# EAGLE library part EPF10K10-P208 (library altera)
EPF10K10 FLEX 10K family
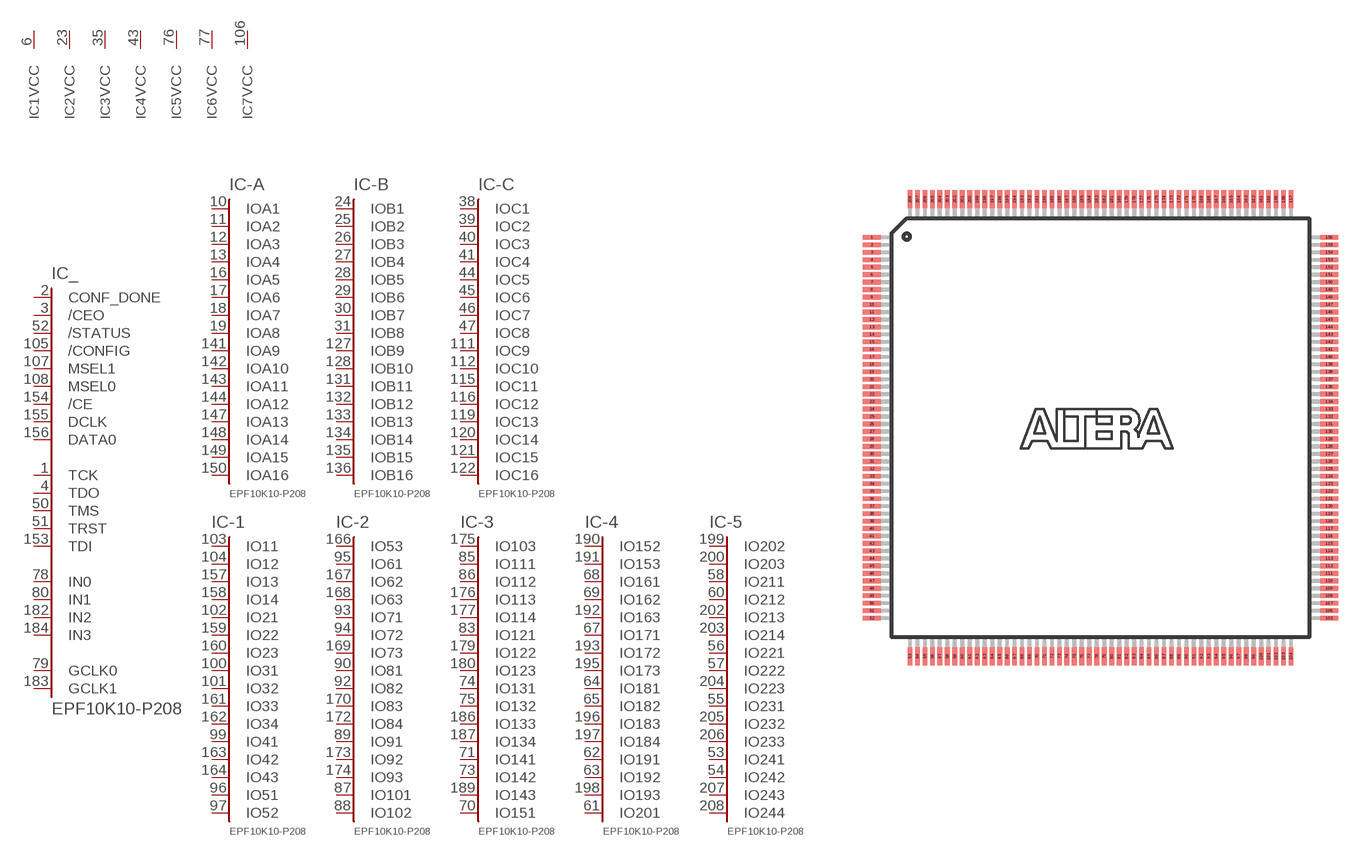
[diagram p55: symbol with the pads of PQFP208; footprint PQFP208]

Designator prefix IC; gates _=K10-CTRL -A=A16 -B=B16 -C=C16 -1=52-K10 -2=102-K10 -3=151-K10 -4=201-K10 -5=244-K10 1=VCCINT 2=VCCINT 3=VCCINT 4=VCCINT 5=VCCINT 6=VCCINT 7=VCCINT 8=VCCINT 9=VCCINT 10=VCCINT 11=VCCINT 12=VCCINT 13=VCCIO 14=VCCIO 15=VCCIO 16=VCCIO 17=VCCIO 18=VCCIO 19=VCCIO 20=VCCIO 21=VCCIO 22=VCCIO 23=VCCIO 24=VCCIO 25=VCCIO 26=VCCIO 27=GNDINT 28=GNDINT 29=GNDINT 30=GNDINT 31=GNDINT 32=GNDINT 33=GNDINT 34=GNDINT 35=GNDINT 36=GNDIO 37=GNDIO 38=GNDIO 39=GNDIO 40=GNDIO 41=GNDIO 42=GNDIO 43=GNDIO 44=GNDIO 45=GNDIO 46=GNDIO 47=GNDIO NC1=NC NC2=NC NC3=NC NC4=NC NC5=NC NC6=NC NC7=NC NC8=NC NC9=NC NC10=NC NC11=NC NC12=NC NC13=NC

## EPF10K10-P208 (MPN: EPF10K10AQC208-3N; OC_FARNELL: 1549381; OC_NEWARK: 51R8749)  [PQFP208]
1  _:TCK
2  _:CONF_DONE  in
3  _:/CEO  in
4  _:TDO
5  13:VCCIO  pwr
6  1:VCC  pwr
7  NC1:NC  nc
8  NC2:NC  nc
9  NC3:NC  nc
10  -A:IOA1
11  -A:IOA2
12  -A:IOA3
13  -A:IOA4
14  NC4:NC  nc
15  NC5:NC  nc
16  -A:IOA5
17  -A:IOA6
18  -A:IOA7
19  -A:IOA8
20  36:GNDIO  pwr
21  27:GND  pwr
22  14:VCCIO  pwr
23  2:VCC  pwr
24  -B:IOB1
25  -B:IOB2
26  -B:IOB3
27  -B:IOB4
28  -B:IOB5
29  -B:IOB6
30  -B:IOB7
31  -B:IOB8
32  37:GNDIO  pwr
33  28:GND  pwr
34  15:VCCIO  pwr
35  3:VCC  pwr
36  NC6:NC  nc
37  NC7:NC  nc
38  -C:IOC1
39  -C:IOC2
40  -C:IOC3
41  -C:IOC4
42  16:VCCIO  pwr
43  4:VCC  pwr
44  -C:IOC5
45  -C:IOC6
46  -C:IOC7
47  -C:IOC8
48  38:GNDIO  pwr
49  29:GND  pwr
50  _:TMS
51  _:TRST
52  _:/STATUS  in
53  -5:IO241
54  -5:IO242
55  -5:IO231
56  -5:IO221
57  -5:IO222
58  -5:IO211
59  39:GNDIO  pwr
60  -5:IO212
61  -4:IO201
62  -4:IO191
63  -4:IO192
64  -4:IO181
65  -4:IO182
66  17:VCCIO  pwr
67  -4:IO171
68  -4:IO161
69  -4:IO162
70  -3:IO151
71  -3:IO141
72  40:GNDIO  pwr
73  -3:IO142
74  -3:IO131
75  -3:IO132
76  5:VCC  pwr
77  6:VCC  pwr
78  _:IN0  in
79  _:GCLK0  in
80  _:IN1  in
81  30:GND  pwr
82  31:GND  pwr
83  -3:IO121
84  18:VCCIO  pwr
85  -3:IO111
86  -3:IO112
87  -2:IO101
88  -2:IO102
89  -2:IO91
90  -2:IO81
91  41:GNDIO  pwr
92  -2:IO82
93  -2:IO71
94  -2:IO72
95  -2:IO61
96  -1:IO51
97  -1:IO52
98  19:VCCIO  pwr
99  -1:IO41
100  -1:IO31
101  -1:IO32
102  -1:IO21
103  -1:IO11
104  -1:IO12
105  _:/CONFIG  in
106  7:VCC  pwr
107  _:MSEL1  in
108  _:MSEL0  in
109  8:VCC  pwr
110  20:VCCIO  pwr
111  -C:IOC9
112  -C:IOC10
113  NC8:NC  nc
114  NC9:NC  nc
115  -C:IOC11
116  -C:IOC12
117  9:VCC  pwr
118  21:VCCIO  pwr
119  -C:IOC13
120  -C:IOC14
121  -C:IOC15
122  -C:IOC16
123  32:GND  pwr
124  42:GNDIO  pwr
125  NC10:NC  nc
126  NC11:NC  nc
127  -B:IOB9
128  -B:IOB10
129  33:GND  pwr
130  43:GNDIO  pwr
131  -B:IOB11
132  -B:IOB12
133  -B:IOB13
134  -B:IOB14
135  -B:IOB15
136  -B:IOB16
137  10:VCC  pwr
138  22:VCCIO  pwr
139  NC12:NC  nc
140  NC13:NC  nc
141  -A:IOA9
142  -A:IOA10
143  -A:IOA11
144  -A:IOA12
145  11:VCC  pwr
146  23:VCCIO  pwr
147  -A:IOA13
148  -A:IOA14
149  -A:IOA15
150  -A:IOA16
151  34:GND  pwr
152  44:GNDIO  pwr
153  _:TDI
154  _:/CE  in
155  _:DCLK  in
156  _:DATA0  in
157  -1:IO13
158  -1:IO14
159  -1:IO22
160  -1:IO23
161  -1:IO33
162  -1:IO34
163  -1:IO42
164  -1:IO43
165  24:VCCIO  pwr
166  -2:IO53
167  -2:IO62
168  -2:IO63
169  -2:IO73
170  -2:IO83
171  45:GNDIO  pwr
172  -2:IO84
173  -2:IO92
174  -2:IO93
175  -3:IO103
176  -3:IO113
177  -3:IO114
178  25:VCCIO  pwr
179  -3:IO122
180  -3:IO123
181  12:VCC  pwr
182  _:IN2  in
183  _:GCLK1  in
184  _:IN3  in
185  35:GND  pwr
186  -3:IO133
187  -3:IO134
188  46:GNDIO  pwr
189  -3:IO143
190  -4:IO152
191  -4:IO153
192  -4:IO163
193  -4:IO172
194  26:VCCIO  pwr
195  -4:IO173
196  -4:IO183
197  -4:IO184
198  -4:IO193
199  -5:IO202
200  -5:IO203
201  47:GNDIO  pwr
202  -5:IO213
203  -5:IO214
204  -5:IO223
205  -5:IO232
206  -5:IO233
207  -5:IO243
208  -5:IO244

## Footprint PQFP208 (pad centres in mm)
Plastic Quad Flat Pack
smd 1.2 x 0.32: 1 -15.3,12.75; 2 -15.3,12.25; 3 -15.3,11.75; 4 -15.3,11.25; 5 -15.3,10.75; 6 -15.3,10.25; 7 -15.3,9.75; 8 -15.3,9.25; 9 -15.3,8.75; 10 -15.3,8.25; 11 -15.3,7.75; 12 -15.3,7.25; 13 -15.3,6.75; 14 -15.3,6.25; 15 -15.3,5.75; 16 -15.3,5.25; 17 -15.3,4.75; 18 -15.3,4.25; 19 -15.3,3.75; 20 -15.3,3.25; 21 -15.3,2.75; 22 -15.3,2.25; 23 -15.3,1.75; 24 -15.3,1.25; 25 -15.3,0.75; 26 -15.3,0.25; 27 -15.3,-0.25; 28 -15.3,-0.75; 29 -15.3,-1.25; 30 -15.3,-1.75; 31 -15.3,-2.25; 32 -15.3,-2.75; 33 -15.3,-3.25; 34 -15.3,-3.75; 35 -15.3,-4.25; 36 -15.3,-4.75; 37 -15.3,-5.25; 38 -15.3,-5.75; 39 -15.3,-6.25; 40 -15.3,-6.75; 41 -15.3,-7.25; 42 -15.3,-7.75; 43 -15.3,-8.25; 44 -15.3,-8.75; 45 -15.3,-9.25; 46 -15.3,-9.75; 47 -15.3,-10.25; 48 -15.3,-10.75; 49 -15.3,-11.25; 50 -15.3,-11.75; 51 -15.3,-12.25; 52 -15.3,-12.75; 105 15.3,-12.75; 106 15.3,-12.25; 107 15.3,-11.75; 108 15.3,-11.25; 109 15.3,-10.75; 110 15.3,-10.25; 111 15.3,-9.75; 112 15.3,-9.25; 113 15.3,-8.75; 114 15.3,-8.25; 115 15.3,-7.75; 116 15.3,-7.25; 117 15.3,-6.75; 118 15.3,-6.25; 119 15.3,-5.75; 120 15.3,-5.25; 121 15.3,-4.75; 122 15.3,-4.25; 123 15.3,-3.75; 124 15.3,-3.25; 125 15.3,-2.75; 126 15.3,-2.25; 127 15.3,-1.75; 128 15.3,-1.25; 129 15.3,-0.75; 130 15.3,-0.25; 131 15.3,0.25; 132 15.3,0.75; 133 15.3,1.25; 134 15.3,1.75; 135 15.3,2.25; 136 15.3,2.75; 137 15.3,3.25; 138 15.3,3.75; 139 15.3,4.25; 140 15.3,4.75; 141 15.3,5.25; 142 15.3,5.75; 143 15.3,6.25; 144 15.3,6.75; 145 15.3,7.25; 146 15.3,7.75; 147 15.3,8.25; 148 15.3,8.75; 149 15.3,9.25; 150 15.3,9.75; 151 15.3,10.25; 152 15.3,10.75; 153 15.3,11.25; 154 15.3,11.75; 155 15.3,12.25; 156 15.3,12.75
smd 0.32 x 1.2: 53 -12.75,-15.3; 54 -12.25,-15.3; 55 -11.75,-15.3; 56 -11.25,-15.3; 57 -10.75,-15.3; 58 -10.25,-15.3; 59 -9.75,-15.3; 60 -9.25,-15.3; 61 -8.75,-15.3; 62 -8.25,-15.3; 63 -7.75,-15.3; 64 -7.25,-15.3; 65 -6.75,-15.3; 66 -6.25,-15.3; 67 -5.75,-15.3; 68 -5.25,-15.3; 69 -4.75,-15.3; 70 -4.25,-15.3; 71 -3.75,-15.3; 72 -3.25,-15.3; 73 -2.75,-15.3; 74 -2.25,-15.3; 75 -1.75,-15.3; 76 -1.25,-15.3; 77 -0.75,-15.3; 78 -0.25,-15.3; 79 0.25,-15.3; 80 0.75,-15.3; 81 1.25,-15.3; 82 1.75,-15.3; 83 2.25,-15.3; 84 2.75,-15.3; 85 3.25,-15.3; 86 3.75,-15.3; 87 4.25,-15.3; 88 4.75,-15.3; 89 5.25,-15.3; 90 5.75,-15.3; 91 6.25,-15.3; 92 6.75,-15.3; 93 7.25,-15.3; 94 7.75,-15.3; 95 8.25,-15.3; 96 8.75,-15.3; 97 9.25,-15.3; 98 9.75,-15.3; 99 10.25,-15.3; 100 10.75,-15.3; 101 11.25,-15.3; 102 11.75,-15.3; 103 12.25,-15.3; 104 12.75,-15.3; 157 12.75,15.3; 158 12.25,15.3; 159 11.75,15.3; 160 11.25,15.3; 161 10.75,15.3; 162 10.25,15.3; 163 9.75,15.3; 164 9.25,15.3; 165 8.75,15.3; 166 8.25,15.3; 167 7.75,15.3; 168 7.25,15.3; 169 6.75,15.3; 170 6.25,15.3; 171 5.75,15.3; 172 5.25,15.3; 173 4.75,15.3; 174 4.25,15.3; 175 3.75,15.3; 176 3.25,15.3; 177 2.75,15.3; 178 2.25,15.3; 179 1.75,15.3; 180 1.25,15.3; 181 0.75,15.3; 182 0.25,15.3; 183 -0.25,15.3; 184 -0.75,15.3; 185 -1.25,15.3; 186 -1.75,15.3; 187 -2.25,15.3; 188 -2.75,15.3; 189 -3.25,15.3; 190 -3.75,15.3; 191 -4.25,15.3; 192 -4.75,15.3; 193 -5.25,15.3; 194 -5.75,15.3; 195 -6.25,15.3; 196 -6.75,15.3; 197 -7.25,15.3; 198 -7.75,15.3; 199 -8.25,15.3; 200 -8.75,15.3; 201 -9.25,15.3; 202 -9.75,15.3; 203 -10.25,15.3; 204 -10.75,15.3; 205 -11.25,15.3; 206 -11.75,15.3; 207 -12.25,15.3; 208 -12.75,15.3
